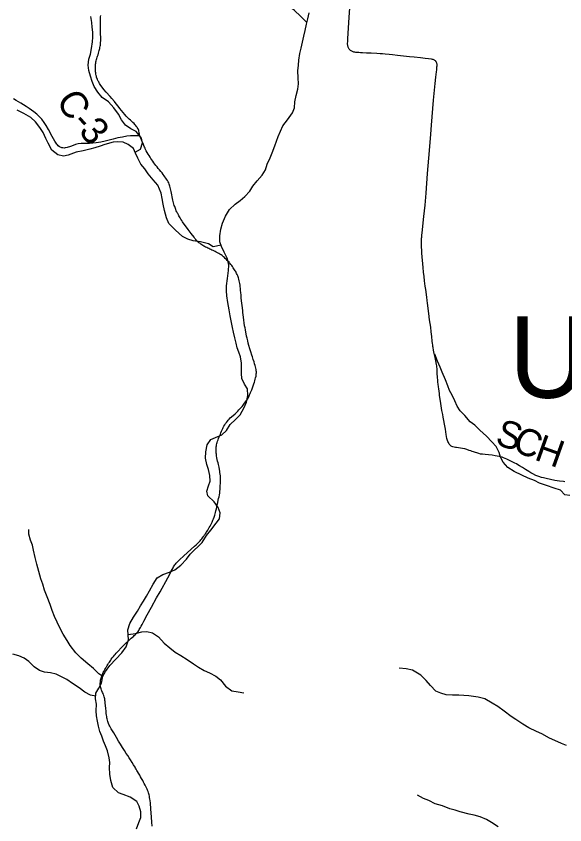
# Model space of a CAD drawing. Extents: x 0 to 34, y 0 to 22.
# Drawn here: x 4.632 to 5.781, y 18.618 to 20.31 of the extents above; entities that cross this region are included whole.
import ezdxf

# ---------------------------------------------------------------- set-up
doc = ezdxf.new("R2010")
doc.units = 0
for name, color, linetype in [('GM_X_County_Road', 7, 'Continuous'), ('GM_X_County_Road_Text', 7, 'Continuous'), ('GM_X_Minor_River', 7, 'Continuous'), ('GM_X_Township_Road', 7, 'Continuous'), ('GM_X_Township_Road_Text', 7, 'Continuous'), ('GM_X_Township_Text', 7, 'Continuous')]:
    doc.layers.add(name, color=color, linetype=linetype)

msp = doc.modelspace()

# ---------------------------------------------------------------- linework, layer by layer
at = {"layer": 'GM_X_County_Road'}
for points in [[(4.8907, 20.0596), (4.8893, 20.0665), (4.8888, 20.0688), (4.8884, 20.0707), (4.8878, 20.0726), (4.8871, 20.074), (4.8854, 20.0767), (4.8844, 20.0781), (4.8832, 20.0797), (4.8816, 20.0816), (4.8804, 20.0831), (4.8787, 20.0849), (4.8764, 20.0872), (4.8742, 20.0893), (4.8716, 20.0919), (4.8688, 20.0944), (4.8665, 20.0965), (4.8645, 20.0985), (4.8624, 20.1007), (4.8595, 20.1039), (4.856, 20.108), (4.8527, 20.1119), (4.8492, 20.1162), (4.8453, 20.1213), (4.8411, 20.1265), (4.8375, 20.1309), (4.8323, 20.1371), (4.8285, 20.1414), (4.8204, 20.1509), (4.8154, 20.1564), (4.8116, 20.1611), (4.8091, 20.1645), (4.8079, 20.1663), (4.8066, 20.1684), (4.8057, 20.17), (4.8047, 20.1719), (4.8038, 20.1736), (4.8031, 20.1752), (4.802, 20.1776), (4.8011, 20.1799), (4.8003, 20.1821), (4.7998, 20.184), (4.7994, 20.1858), (4.799, 20.188), (4.7986, 20.1907), (4.7983, 20.1931), (4.7981, 20.1958), (4.7979, 20.1986), (4.7978, 20.2015), (4.7978, 20.2039), (4.7979, 20.206), (4.7981, 20.209), (4.7986, 20.2115), (4.799, 20.2139), (4.7995, 20.2161), (4.8001, 20.2189), (4.8008, 20.2212), (4.8016, 20.2238), (4.8023, 20.2261), (4.8033, 20.2287), (4.8045, 20.2324), (4.8053, 20.2351), (4.806, 20.2376), (4.8065, 20.2397), (4.807, 20.242), (4.8074, 20.244), (4.808, 20.2469), (4.8083, 20.2492), (4.8086, 20.252), (4.8088, 20.2546), (4.8089, 20.2581), (4.809, 20.262), (4.8089, 20.2668), (4.8088, 20.2708), (4.8085, 20.2761), (4.8084, 20.2812), (4.8084, 20.2864), (4.8083, 20.2925), (4.8084, 20.3007), (4.8085, 20.3046), (4.8087, 20.3082), (4.8089, 20.311)], [(4.8907, 20.0596), (4.8807, 20.0595), (4.8764, 20.0594), (4.8714, 20.0592), (4.8633, 20.0583), (4.8547, 20.0568), (4.845, 20.0549), (4.8353, 20.0525), (4.8179, 20.0481), (4.8094, 20.0463), (4.7991, 20.0446), (4.7924, 20.0439), (4.7856, 20.0434), (4.775, 20.0433), (4.7682, 20.043), (4.7619, 20.0422), (4.7564, 20.0408), (4.7511, 20.039), (4.7458, 20.0371), (4.7388, 20.0348), (4.7347, 20.034), (4.7324, 20.0338), (4.7298, 20.034), (4.7277, 20.0344), (4.7261, 20.035), (4.7229, 20.0365), (4.72, 20.0386), (4.7183, 20.0403), (4.7168, 20.0418), (4.7156, 20.0436), (4.7127, 20.0483), (4.7075, 20.0581), (4.6999, 20.0724), (4.6948, 20.081), (4.6907, 20.0873), (4.6857, 20.0938), (4.6806, 20.0993), (4.675, 20.1043), (4.6686, 20.1093), (4.6589, 20.1162), (4.6528, 20.1204), (4.6413, 20.1279), (4.637, 20.1304), (4.6321, 20.1333), (4.626, 20.1364)], [(4.9164, 18.6156), (4.9158, 18.6237), (4.9152, 18.634), (4.9139, 18.6513), (4.9129, 18.6637), (4.9123, 18.6689), (4.9119, 18.672), (4.9114, 18.6753), (4.9109, 18.6783), (4.9103, 18.6809), (4.9097, 18.6831), (4.9091, 18.6854), (4.9083, 18.6878), (4.9072, 18.6904), (4.9061, 18.6928), (4.9047, 18.6955), (4.9033, 18.6984), (4.9017, 18.7014), (4.9, 18.7046), (4.8984, 18.7076), (4.8968, 18.7108), (4.8945, 18.7149), (4.8924, 18.7185), (4.8907, 18.7217), (4.888, 18.7265), (4.886, 18.73), (4.8848, 18.7321), (4.8833, 18.7346), (4.882, 18.7365), (4.8807, 18.7388), (4.8778, 18.7435), (4.8745, 18.7488), (4.8711, 18.7542), (4.8686, 18.7581), (4.8656, 18.7629), (4.8625, 18.7677), (4.8588, 18.7733), (4.8545, 18.7798), (4.85, 18.787), (4.8464, 18.7931), (4.8419, 18.8008), (4.8389, 18.8057), (4.8361, 18.8103), (4.8333, 18.8149), (4.8309, 18.819), (4.8294, 18.8217), (4.8278, 18.8244), (4.8266, 18.8269), (4.8254, 18.8298), (4.8246, 18.8322), (4.8238, 18.8346), (4.823, 18.8372), (4.8225, 18.8397), (4.8219, 18.8422), (4.8215, 18.8447), (4.8211, 18.8473), (4.8206, 18.8509), (4.82, 18.8558), (4.8195, 18.8616), (4.8184, 18.8732), (4.8181, 18.8764), (4.8178, 18.8784), (4.8176, 18.88), (4.8173, 18.882), (4.8169, 18.8841), (4.8163, 18.8861), (4.8155, 18.8884), (4.8146, 18.8904), (4.8137, 18.8925), (4.8126, 18.8949), (4.8112, 18.8981), (4.8104, 18.9001), (4.8096, 18.9024), (4.809, 18.9045), (4.8084, 18.907), (4.8081, 18.9089), (4.808, 18.911), (4.808, 18.9125), (4.8081, 18.9146), (4.8082, 18.9171), (4.8085, 18.9188), (4.8088, 18.9207), (4.8093, 18.923), (4.8098, 18.9249), (4.8104, 18.9271), (4.8112, 18.9294), (4.8122, 18.9319), (4.8132, 18.9346), (4.8142, 18.9369), (4.8153, 18.9391), (4.816, 18.9406), (4.8172, 18.9427), (4.8186, 18.945), (4.8198, 18.947), (4.8209, 18.9489), (4.8222, 18.9512), (4.8238, 18.9538), (4.8253, 18.9561), (4.827, 18.9586), (4.8284, 18.9606), (4.8298, 18.9627), (4.8311, 18.9645), (4.8331, 18.9671), (4.8354, 18.9701), (4.8375, 18.9727), (4.8393, 18.9747), (4.8413, 18.9771), (4.8442, 18.9803), (4.853, 18.9895), (4.8562, 18.9928), (4.8607, 18.9972), (4.863, 18.9994), (4.8656, 19.0019), (4.8682, 19.0043), (4.8707, 19.0065), (4.8728, 19.0084), (4.8753, 19.0106), (4.8774, 19.0124), (4.8793, 19.0141), (4.8807, 19.0155), (4.8821, 19.0168), (4.8834, 19.0181), (4.8848, 19.0195), (4.8861, 19.021), (4.8871, 19.0226), (4.8884, 19.0246), (4.8894, 19.0264), (4.8908, 19.0285), (4.8919, 19.0306), (4.8935, 19.0337), (4.8955, 19.0374), (4.8991, 19.044), (4.9065, 19.0577), (4.9151, 19.0735), (4.9259, 19.0927), (4.9331, 19.1058), (4.9496, 19.1348), (4.9549, 19.1449), (4.9567, 19.1485), (4.9586, 19.1521), (4.9604, 19.1556), (4.9615, 19.1577), (4.9629, 19.16), (4.9644, 19.162), (4.9657, 19.1637), (4.967, 19.1653), (4.9687, 19.1672), (4.9702, 19.1688), (4.9717, 19.1705), (4.9737, 19.1723), (4.9827, 19.1806), (5.0051, 19.2007), (5.0085, 19.2037), (5.0114, 19.2066), (5.0142, 19.2095), (5.0169, 19.2124), (5.0187, 19.2145), (5.0205, 19.2164), (5.0219, 19.2185), (5.0232, 19.2202), (5.0247, 19.2222), (5.0265, 19.2246), (5.028, 19.2268), (5.0294, 19.2288), (5.0304, 19.2306), (5.0315, 19.2324), (5.0331, 19.2348), (5.0346, 19.2374), (5.0362, 19.2401), (5.0378, 19.2429), (5.0392, 19.2454), (5.0406, 19.2482), (5.042, 19.251), (5.043, 19.2533), (5.044, 19.2556), (5.0449, 19.2579), (5.0465, 19.262), (5.0477, 19.2656), (5.0486, 19.2686), (5.0494, 19.2717), (5.0502, 19.2752), (5.0511, 19.2789), (5.052, 19.2835), (5.0529, 19.2875), (5.054, 19.2925), (5.055, 19.2971), (5.0558, 19.301), (5.0566, 19.3044), (5.0573, 19.3084), (5.058, 19.3122), (5.0585, 19.3162), (5.0588, 19.3197), (5.059, 19.3236), (5.0593, 19.3281), (5.0595, 19.3323), (5.0597, 19.3363), (5.0598, 19.3406), (5.0597, 19.3446), (5.0594, 19.3481), (5.0591, 19.3517), (5.0586, 19.3549), (5.058, 19.3581), (5.0574, 19.3616), (5.0566, 19.3659), (5.056, 19.3687), (5.0552, 19.372), (5.0545, 19.3752), (5.0537, 19.3787), (5.0529, 19.382), (5.0523, 19.3857), (5.0516, 19.3899), (5.0512, 19.3931), (5.0509, 19.3954), (5.0507, 19.3975), (5.0506, 19.4001), (5.0506, 19.4029), (5.0507, 19.406), (5.051, 19.4087), (5.0513, 19.411), (5.0516, 19.4133), (5.0521, 19.4157), (5.0527, 19.4179), (5.0535, 19.4204), (5.0545, 19.4233), (5.0557, 19.4264), (5.0569, 19.4297), (5.058, 19.4323), (5.0594, 19.4355), (5.0605, 19.4381), (5.062, 19.4415), (5.0633, 19.4444), (5.0645, 19.4468), (5.0655, 19.449), (5.067, 19.4518), (5.0686, 19.4547), (5.0704, 19.4574), (5.072, 19.4597), (5.0743, 19.4628), (5.076, 19.4648), (5.0779, 19.4667), (5.0802, 19.4691), (5.0863, 19.4746), (5.0902, 19.4781), (5.0932, 19.4809), (5.0962, 19.4837), (5.0983, 19.4859), (5.1017, 19.4894), (5.1037, 19.4915), (5.1053, 19.4934), (5.1072, 19.4957), (5.1103, 19.4999), (5.1124, 19.5027), (5.1146, 19.5063), (5.1162, 19.5088), (5.1181, 19.5123), (5.1195, 19.5151), (5.1207, 19.5174), (5.1218, 19.5201), (5.1227, 19.5224), (5.1238, 19.525), (5.125, 19.5282), (5.1264, 19.5321), (5.1281, 19.5366), (5.1295, 19.5404), (5.1308, 19.5442), (5.1317, 19.547), (5.1326, 19.5501), (5.1333, 19.5529), (5.1342, 19.5566), (5.1345, 19.559), (5.1347, 19.5614), (5.1348, 19.5633), (5.1348, 19.5657), (5.1347, 19.5679), (5.1344, 19.5705), (5.1339, 19.5731), (5.1332, 19.5761), (5.1323, 19.5791), (5.1312, 19.5826), (5.13, 19.5863), (5.1284, 19.5911), (5.1266, 19.5967), (5.1253, 19.6008), (5.1232, 19.6073), (5.1213, 19.6139), (5.1193, 19.6205), (5.1179, 19.6257), (5.1167, 19.6305), (5.1154, 19.6361), (5.1145, 19.6403), (5.1135, 19.645), (5.1127, 19.6487), (5.1119, 19.6532), (5.1111, 19.6579), (5.1103, 19.662), (5.1093, 19.6682), (5.1085, 19.6736), (5.1077, 19.68), (5.1071, 19.685), (5.1066, 19.6899), (5.1062, 19.6937), (5.1033, 19.7197), (5.1028, 19.7264), (5.1024, 19.7309), (5.1019, 19.7363), (5.1015, 19.7404), (5.1012, 19.7436), (5.1008, 19.747), (5.1003, 19.7502), (5.0997, 19.7529), (5.099, 19.7562), (5.0981, 19.7593), (5.0971, 19.7622), (5.0957, 19.7661), (5.0945, 19.7689), (5.0935, 19.7713), (5.0925, 19.7733), (5.0915, 19.7752), (5.0904, 19.7772), (5.0892, 19.7793), (5.0879, 19.7814), (5.0865, 19.7834), (5.085, 19.7857), (5.0832, 19.788), (5.0813, 19.7903), (5.0789, 19.7933), (5.0776, 19.7947), (5.0754, 19.7972), (5.074, 19.7987), (5.072, 19.8008), (5.0698, 19.8029), (5.068, 19.8047), (5.0662, 19.8062), (5.0646, 19.8075), (5.063, 19.8088), (5.0609, 19.8102), (5.0584, 19.8117), (5.0562, 19.813), (5.0538, 19.8144), (5.051, 19.8158), (5.0483, 19.8172), (5.0441, 19.8192), (5.0415, 19.8204), (5.0392, 19.8215), (5.0371, 19.8225), (5.0351, 19.8234), (5.0331, 19.8243), (5.0309, 19.8254), (5.0285, 19.8266), (5.0263, 19.8278), (5.0247, 19.8288), (5.0225, 19.8301), (5.0206, 19.8314), (5.0183, 19.833), (5.0162, 19.8345), (5.0147, 19.8357), (5.0131, 19.8372), (5.0112, 19.839), (5.0098, 19.8405), (5.0082, 19.8423), (5.0062, 19.8448), (5.0044, 19.8471), (4.9986, 19.8548), (4.992, 19.8636), (4.9804, 19.8795), (4.9785, 19.8823), (4.9769, 19.8848), (4.9752, 19.8876), (4.9739, 19.8897), (4.9727, 19.8917), (4.9715, 19.8939), (4.9701, 19.8966), (4.9693, 19.8983), (4.9682, 19.9005), (4.9672, 19.9026), (4.9662, 19.905), (4.9654, 19.9071), (4.9645, 19.9094), (4.9638, 19.9114), (4.9629, 19.9137), (4.9623, 19.916), (4.9615, 19.919), (4.9606, 19.9221), (4.9599, 19.9249), (4.9592, 19.9282), (4.9584, 19.9318), (4.9576, 19.9358), (4.9568, 19.9396), (4.9562, 19.9425), (4.9555, 19.9459), (4.955, 19.9484), (4.9544, 19.9509), (4.9535, 19.9541), (4.9528, 19.9563), (4.9521, 19.9585), (4.9512, 19.9608), (4.95, 19.9632), (4.9487, 19.9656), (4.947, 19.9685), (4.9454, 19.9709), (4.9435, 19.9736), (4.9421, 19.9756), (4.9398, 19.9785), (4.9374, 19.9816), (4.935, 19.9845), (4.9322, 19.9878), (4.9294, 19.9912), (4.9268, 19.9944), (4.9245, 19.9973), (4.9224, 20.0001), (4.9204, 20.0029), (4.918, 20.0065), (4.9161, 20.0093), (4.9142, 20.012), (4.9123, 20.0146), (4.9101, 20.018), (4.9081, 20.021), (4.9062, 20.0242), (4.9043, 20.0278), (4.9027, 20.0309), (4.9017, 20.0332), (4.9005, 20.0357), (4.8991, 20.0393), (4.8977, 20.043), (4.8959, 20.0472), (4.8907, 20.0596)]]:
    msp.add_lwpolyline(points, dxfattribs=at)
at = {"layer": 'GM_X_Minor_River'}
for points in [[(5.2407, 20.2964), (5.2377, 20.299), (5.228, 20.3086), (5.2137, 20.3221), (5.2013, 20.3314), (5.1904, 20.3368), (5.1761, 20.3476), (5.163, 20.3592), (5.1532, 20.3658), (5.1412, 20.3765), (5.133, 20.3865), (5.1256, 20.398), (5.1171, 20.414), (5.11, 20.4255), (5.0984, 20.4385), (5.0879, 20.447), (5.0756, 20.4589), (5.0681, 20.4723), (5.0667, 20.4818), (5.0661, 20.4951)], [(5.0591, 19.271), (5.055, 19.2821), (5.0464, 19.2936), (5.033, 19.3066), (5.0312, 19.3161), (5.0347, 19.3271), (5.0383, 19.3373), (5.0373, 19.3491), (5.0344, 19.3612), (5.0311, 19.3715), (5.0286, 19.3848), (5.0292, 19.3985), (5.032, 19.4128), (5.0394, 19.4241), (5.0493, 19.4285), (5.0622, 19.4337), (5.0726, 19.443), (5.08, 19.4554), (5.0911, 19.4659), (5.1011, 19.476), (5.1096, 19.4907), (5.1139, 19.5024), (5.1171, 19.516), (5.1165, 19.5304), (5.1098, 19.54), (5.1047, 19.5518), (5.1037, 19.5621), (5.1034, 19.5727), (5.1039, 19.5837), (5.1018, 19.597), (5.0982, 19.6065), (5.0949, 19.616), (5.0927, 19.6256), (5.0898, 19.6366), (5.0873, 19.6484), (5.0848, 19.6587), (5.083, 19.6685), (5.0802, 19.6826), (5.0777, 19.6952), (5.0752, 19.7107), (5.0731, 19.7244), (5.0721, 19.7354), (5.0726, 19.7457), (5.0743, 19.7608), (5.0764, 19.7778), (5.0769, 19.7885), (5.0745, 19.8018), (5.0674, 19.8159), (5.0619, 19.8277), (5.0582, 19.8376), (5.058, 19.8498), (5.0605, 19.8638), (5.064, 19.8766), (5.0703, 19.8913), (5.0788, 19.9052), (5.0907, 19.9165), (5.101, 19.9239), (5.1106, 19.9321), (5.121, 19.9434), (5.1272, 19.9543), (5.1364, 19.9652), (5.1472, 19.9771), (5.1538, 19.9881), (5.1577, 20.0001), (5.1636, 20.0133), (5.1682, 20.0239), (5.1734, 20.0382), (5.1804, 20.0579), (5.1851, 20.0692), (5.1906, 20.0801), (5.1998, 20.0929), (5.2103, 20.1075), (5.2146, 20.1181), (5.2151, 20.1306), (5.2183, 20.1438), (5.2219, 20.157), (5.2231, 20.168), (5.2222, 20.1805), (5.222, 20.1953), (5.2229, 20.2071), (5.2241, 20.2173), (5.2262, 20.2313), (5.2286, 20.2427), (5.2311, 20.2551), (5.2343, 20.2676), (5.2371, 20.2797), (5.2399, 20.2929), (5.2423, 20.3039), (5.2451, 20.3164)], [(4.881, 20.0253), (4.8923, 20.0317), (4.8967, 20.0446), (4.8941, 20.0545), (4.8829, 20.0686), (4.872, 20.0737), (4.8611, 20.0818), (4.8525, 20.0929), (4.8459, 20.1044), (4.8366, 20.1178), (4.825, 20.1305), (4.8118, 20.1394), (4.8032, 20.1505), (4.795, 20.1623), (4.791, 20.1726), (4.7877, 20.1844), (4.7837, 20.1959), (4.7823, 20.2069), (4.784, 20.2194), (4.7876, 20.2303), (4.7896, 20.2417), (4.792, 20.2557), (4.7926, 20.2659), (4.7923, 20.2758), (4.7909, 20.2868), (4.7903, 20.2963), (4.7882, 20.3092)], [(5.0608, 19.8307), (5.0444, 19.8272), (5.0347, 19.8334), (5.018, 19.8378), (5.0025, 19.8399), (4.9916, 19.8431), (4.9803, 19.8489), (4.9656, 19.862), (4.9518, 19.8762), (4.9466, 19.888), (4.9423, 19.9029), (4.9394, 19.9166), (4.9373, 19.928), (4.9352, 19.939), (4.9285, 19.9558), (4.9188, 19.9669), (4.9084, 19.9796), (4.9013, 19.9899), (4.8927, 20.0002), (4.8864, 20.0125), (4.882, 20.0231), (4.8776, 20.0327), (4.8667, 20.0408), (4.8557, 20.0459), (4.8451, 20.0468), (4.8349, 20.0458), (4.8174, 20.0414), (4.8075, 20.0374), (4.7968, 20.0341), (4.7858, 20.0312), (4.7721, 20.028), (4.7577, 20.0252), (4.7409, 20.0189), (4.731, 20.0168), (4.7193, 20.0196), (4.7065, 20.0293), (4.6991, 20.0438), (4.6943, 20.0537), (4.6884, 20.0663), (4.6817, 20.077), (4.672, 20.0885), (4.6623, 20.0974), (4.648, 20.1063), (4.634, 20.1129)], [(5.7912, 19.3072), (5.7806, 19.3085), (5.772, 19.3181), (5.7584, 19.3224), (5.7422, 19.3276), (5.7275, 19.3331), (5.7169, 19.3381), (5.7041, 19.3432), (5.6905, 19.3495), (5.6747, 19.3569), (5.6615, 19.3654), (5.6514, 19.3769), (5.6463, 19.3869), (5.643, 19.3968), (5.6367, 19.4094), (5.6277, 19.419), (5.6165, 19.4309), (5.603, 19.4436), (5.5925, 19.4543), (5.5828, 19.4613), (5.5715, 19.4743), (5.5618, 19.4843), (5.5555, 19.4939), (5.5503, 19.5053), (5.5448, 19.5171), (5.5396, 19.5267), (5.5356, 19.5366), (5.5312, 19.5488), (5.5238, 19.5652), (5.5197, 19.5751), (5.5142, 19.5877), (5.5087, 19.6026)], [(4.8835, 18.61), (4.889, 18.6228), (4.8929, 18.6334), (4.8927, 18.6456), (4.8894, 18.6574), (4.8843, 18.6673), (4.8707, 18.6758), (4.856, 18.6813), (4.8462, 18.6852), (4.8346, 18.696), (4.8302, 18.7112), (4.8281, 18.7242), (4.8275, 18.7382), (4.8277, 18.7488), (4.8266, 18.7583), (4.8234, 18.7728), (4.819, 18.7831), (4.8149, 18.7934), (4.8109, 18.8036), (4.8072, 18.8132), (4.804, 18.8242), (4.8022, 18.8349), (4.8001, 18.8459), (4.7991, 18.8569), (4.8004, 18.8705), (4.7982, 18.8819), (4.7988, 18.8937), (4.8053, 18.9038), (4.8104, 18.9148), (4.8136, 18.9288), (4.8187, 18.9389), (4.8279, 18.9517), (4.8406, 18.9644), (4.8533, 18.9779), (4.8625, 18.9907), (4.8669, 19.0054), (4.8663, 19.0153), (4.866, 19.0263), (4.8696, 19.0392), (4.8773, 19.0523), (4.8862, 19.0651), (4.8924, 19.0764), (4.8986, 19.0862), (4.9048, 19.0963), (4.911, 19.1076), (4.9184, 19.1216), (4.9269, 19.1347), (4.9391, 19.1414), (4.9528, 19.1465), (4.9639, 19.1517), (4.9769, 19.1614), (4.9888, 19.1737), (4.9965, 19.1846), (5.0211, 19.2086), (5.0304, 19.2236), (5.0393, 19.2345), (5.0508, 19.2488), (5.0578, 19.2585), (5.0591, 19.271)], [(4.8135, 18.9283), (4.8053, 18.9342), (4.7937, 18.9453), (4.7821, 18.955), (4.7678, 18.9665), (4.7566, 18.9781), (4.745, 18.993), (4.7384, 19.0037), (4.7302, 19.0167), (4.7239, 19.0286), (4.7176, 19.0423), (4.7124, 19.0537), (4.7073, 19.0663), (4.7033, 19.0793), (4.6967, 19.0953), (4.6915, 19.109), (4.6875, 19.1216), (4.6835, 19.1326), (4.6748, 19.1635), (4.6715, 19.1775), (4.6683, 19.1928), (4.6662, 19.2034), (4.6621, 19.2133), (4.6585, 19.2263), (4.6582, 19.2358)], [(4.8662, 19.0166), (4.8819, 19.0185), (4.8952, 19.0217), (4.9058, 19.0227), (4.9175, 19.0199), (4.9299, 19.0114), (4.9419, 18.9984), (4.9535, 18.9884), (4.9648, 18.9795), (4.9768, 18.9725), (4.99, 18.964), (5.0035, 18.9547), (5.0137, 18.9481), (5.0257, 18.9411), (5.037, 18.9361), (5.0498, 18.9294), (5.0596, 18.9213), (5.07, 18.9083), (5.0832, 18.8987), (5.0968, 18.8962), (5.1089, 18.8945)], [(4.7985, 18.887), (4.7877, 18.8893), (4.7757, 18.8955), (4.764, 18.9044), (4.7501, 18.9141), (4.7381, 18.9218), (4.7283, 18.9272), (4.7159, 18.9331), (4.7041, 18.9363), (4.6913, 18.9372), (4.6807, 18.9408), (4.6694, 18.9485), (4.6586, 18.9596), (4.6484, 18.967), (4.6375, 18.9713), (4.625, 18.9753)], [(5.7846, 18.7843), (5.7737, 18.7886), (5.7601, 18.7945), (5.7484, 18.7996), (5.7326, 18.8085), (5.7217, 18.8136), (5.7051, 18.821), (5.6931, 18.8284), (5.6784, 18.8388), (5.6686, 18.845), (5.6536, 18.8562), (5.6405, 18.8655), (5.6284, 18.8728), (5.6134, 18.8814), (5.599, 18.885), (5.5797, 18.8879), (5.5695, 18.8888), (5.5589, 18.8897), (5.5452, 18.8891), (5.5323, 18.89), (5.521, 18.8932), (5.5108, 18.8975), (5.4996, 18.9098), (5.4903, 18.9202), (5.479, 18.9313), (5.4621, 18.9414), (5.4485, 18.9446), (5.4341, 18.946)], [(5.6415, 18.614), (5.6272, 18.6229), (5.6166, 18.6291), (5.6038, 18.635), (5.5906, 18.6382), (5.5804, 18.6406), (5.5615, 18.645), (5.5509, 18.6486), (5.54, 18.6518), (5.5249, 18.6577), (5.509, 18.6624), (5.4962, 18.6687), (5.4849, 18.6734), (5.4721, 18.68)]]:
    msp.add_lwpolyline(points, dxfattribs=at)
at = {"layer": 'GM_X_Township_Road'}
msp.add_lwpolyline([(5.781, 19.3356), (5.778, 19.336), (5.7696, 19.3367), (5.7595, 19.3382), (5.7507, 19.3402), (5.742, 19.3424), (5.7363, 19.3437), (5.7318, 19.3448), (5.726, 19.3466), (5.7203, 19.3489), (5.7138, 19.3523), (5.7099, 19.3546), (5.7054, 19.3571), (5.6985, 19.3615), (5.692, 19.3654), (5.6857, 19.3692), (5.6823, 19.3713), (5.6793, 19.3729), (5.6762, 19.3747), (5.6721, 19.3766), (5.6689, 19.3784), (5.6638, 19.381), (5.6592, 19.3831), (5.656, 19.3845), (5.6524, 19.386), (5.6494, 19.3871), (5.6464, 19.3879), (5.6436, 19.3887), (5.6392, 19.3895), (5.6351, 19.3902), (5.6286, 19.391), (5.6212, 19.3918), (5.6139, 19.3925), (5.6081, 19.3931), (5.6043, 19.3937), (5.6004, 19.3946), (5.5963, 19.3959), (5.5939, 19.3967), (5.5894, 19.3983), (5.5866, 19.3992), (5.5838, 19.4003), (5.5806, 19.4014), (5.5755, 19.4033), (5.5712, 19.4045), (5.5667, 19.4054), (5.5622, 19.4061), (5.5583, 19.4066), (5.5541, 19.4072), (5.5518, 19.4076), (5.5487, 19.4081), (5.546, 19.4087), (5.544, 19.4095), (5.5427, 19.4104), (5.5417, 19.4113), (5.5406, 19.4123), (5.5395, 19.4135), (5.5386, 19.4147), (5.5378, 19.4161), (5.5369, 19.4178), (5.5361, 19.4196), (5.5353, 19.4217), (5.5346, 19.4238), (5.534, 19.4265), (5.5325, 19.4344), (5.5308, 19.4458), (5.529, 19.4565), (5.5276, 19.4639), (5.5263, 19.4706), (5.5251, 19.4767), (5.5235, 19.4847), (5.5211, 19.4991), (5.5202, 19.5046), (5.5192, 19.5121), (5.5186, 19.5169), (5.5181, 19.5205), (5.5169, 19.53), (5.5162, 19.5344), (5.5156, 19.5396), (5.5149, 19.544), (5.5145, 19.5483), (5.5141, 19.5538), (5.5139, 19.5566), (5.5137, 19.5598), (5.5137, 19.563), (5.5137, 19.5658), (5.5135, 19.5689), (5.5133, 19.5727), (5.5129, 19.5754), (5.5125, 19.5784), (5.512, 19.5812), (5.5106, 19.5888), (5.509, 19.5959), (5.5071, 19.604), (5.5058, 19.6109), (5.505, 19.6164), (5.5047, 19.6185), (5.5042, 19.6222), (5.504, 19.625), (5.5033, 19.6298), (5.5022, 19.6393), (5.5011, 19.6492), (5.4999, 19.6591), (5.4987, 19.6666), (5.4976, 19.6744), (5.4957, 19.6875), (5.493, 19.709), (5.4924, 19.7149), (5.4916, 19.722), (5.491, 19.727), (5.4902, 19.7327), (5.4894, 19.738), (5.4884, 19.7447), (5.487, 19.7559), (5.486, 19.7647), (5.4851, 19.7739), (5.4843, 19.7839), (5.4816, 19.8136), (5.481, 19.821), (5.4807, 19.8256), (5.4805, 19.8288), (5.4804, 19.8319), (5.4803, 19.8348), (5.4804, 19.8376), (5.4806, 19.8421), (5.4809, 19.8451), (5.4812, 19.8476), (5.4816, 19.8516), (5.4821, 19.8561), (5.4857, 19.8905), (5.488, 19.9141), (5.4903, 19.9392), (5.4934, 19.9806), (5.4973, 20.0284), (5.5, 20.0629), (5.5014, 20.0815), (5.506, 20.1342), (5.5095, 20.1688), (5.5108, 20.1822), (5.5119, 20.1933), (5.5124, 20.1973), (5.5128, 20.2004), (5.513, 20.2038), (5.5131, 20.2059), (5.5132, 20.2077), (5.5131, 20.2093), (5.5129, 20.2105), (5.5127, 20.2115), (5.5123, 20.2123), (5.5119, 20.2132), (5.5114, 20.214), (5.5109, 20.2147), (5.5104, 20.2154), (5.5096, 20.2161), (5.5087, 20.2168), (5.5076, 20.2175), (5.5063, 20.2182), (5.505, 20.2187), (5.5034, 20.2192), (5.5013, 20.2196), (5.4953, 20.2205), (5.4882, 20.2213), (5.4784, 20.2223), (5.4653, 20.2235), (5.4556, 20.2245), (5.4429, 20.226), (5.4306, 20.2275), (5.4197, 20.2287), (5.4132, 20.2294), (5.4046, 20.2302), (5.399, 20.2307), (5.394, 20.231), (5.3872, 20.2314), (5.3755, 20.2319), (5.3652, 20.2324), (5.3572, 20.2328), (5.3531, 20.233), (5.3495, 20.2333), (5.3463, 20.2335), (5.3433, 20.2339), (5.341, 20.2342), (5.339, 20.2346), (5.3375, 20.235), (5.3363, 20.2354), (5.335, 20.236), (5.3334, 20.2368), (5.3322, 20.2376), (5.3313, 20.2384), (5.3302, 20.2395), (5.3292, 20.2408), (5.3284, 20.2421), (5.3277, 20.2432), (5.3272, 20.2445), (5.3268, 20.2456), (5.3265, 20.247), (5.3262, 20.2486), (5.326, 20.25), (5.3259, 20.2513), (5.326, 20.2533), (5.3261, 20.2556), (5.3265, 20.263), (5.3295, 20.3069), (5.3313, 20.3364)], dxfattribs=at)

# ---------------------------------------------------------------- texts
at = {"layer": 'GM_X_County_Road_Text'}
for s, rotation, p in [('C', 301.0598, (4.7144, 20.1343)), ('-', 311.9968, (4.7455, 20.0848)), ('3', 310.888, (4.761, 20.0677))]:
    msp.add_text(s, height=0.0568, rotation=rotation, dxfattribs=at).set_placement(p)
at = {"layer": 'GM_X_Township_Road_Text'}
for s, rotation, p in [('S', 342.4929, (5.6327, 19.4144)), ('C', 335.7815, (5.6676, 19.4035)), ('H', 340.3962, (5.7148, 19.3825))]:
    msp.add_text(s, height=0.0568, rotation=rotation, dxfattribs=at).set_placement(p)
at = {"layer": 'GM_X_Township_Text'}
msp.add_text('UNION', height=0.17045, rotation=0, dxfattribs=at).set_placement((5.6638, 19.5114))

doc.saveas('drawing.dxf')
